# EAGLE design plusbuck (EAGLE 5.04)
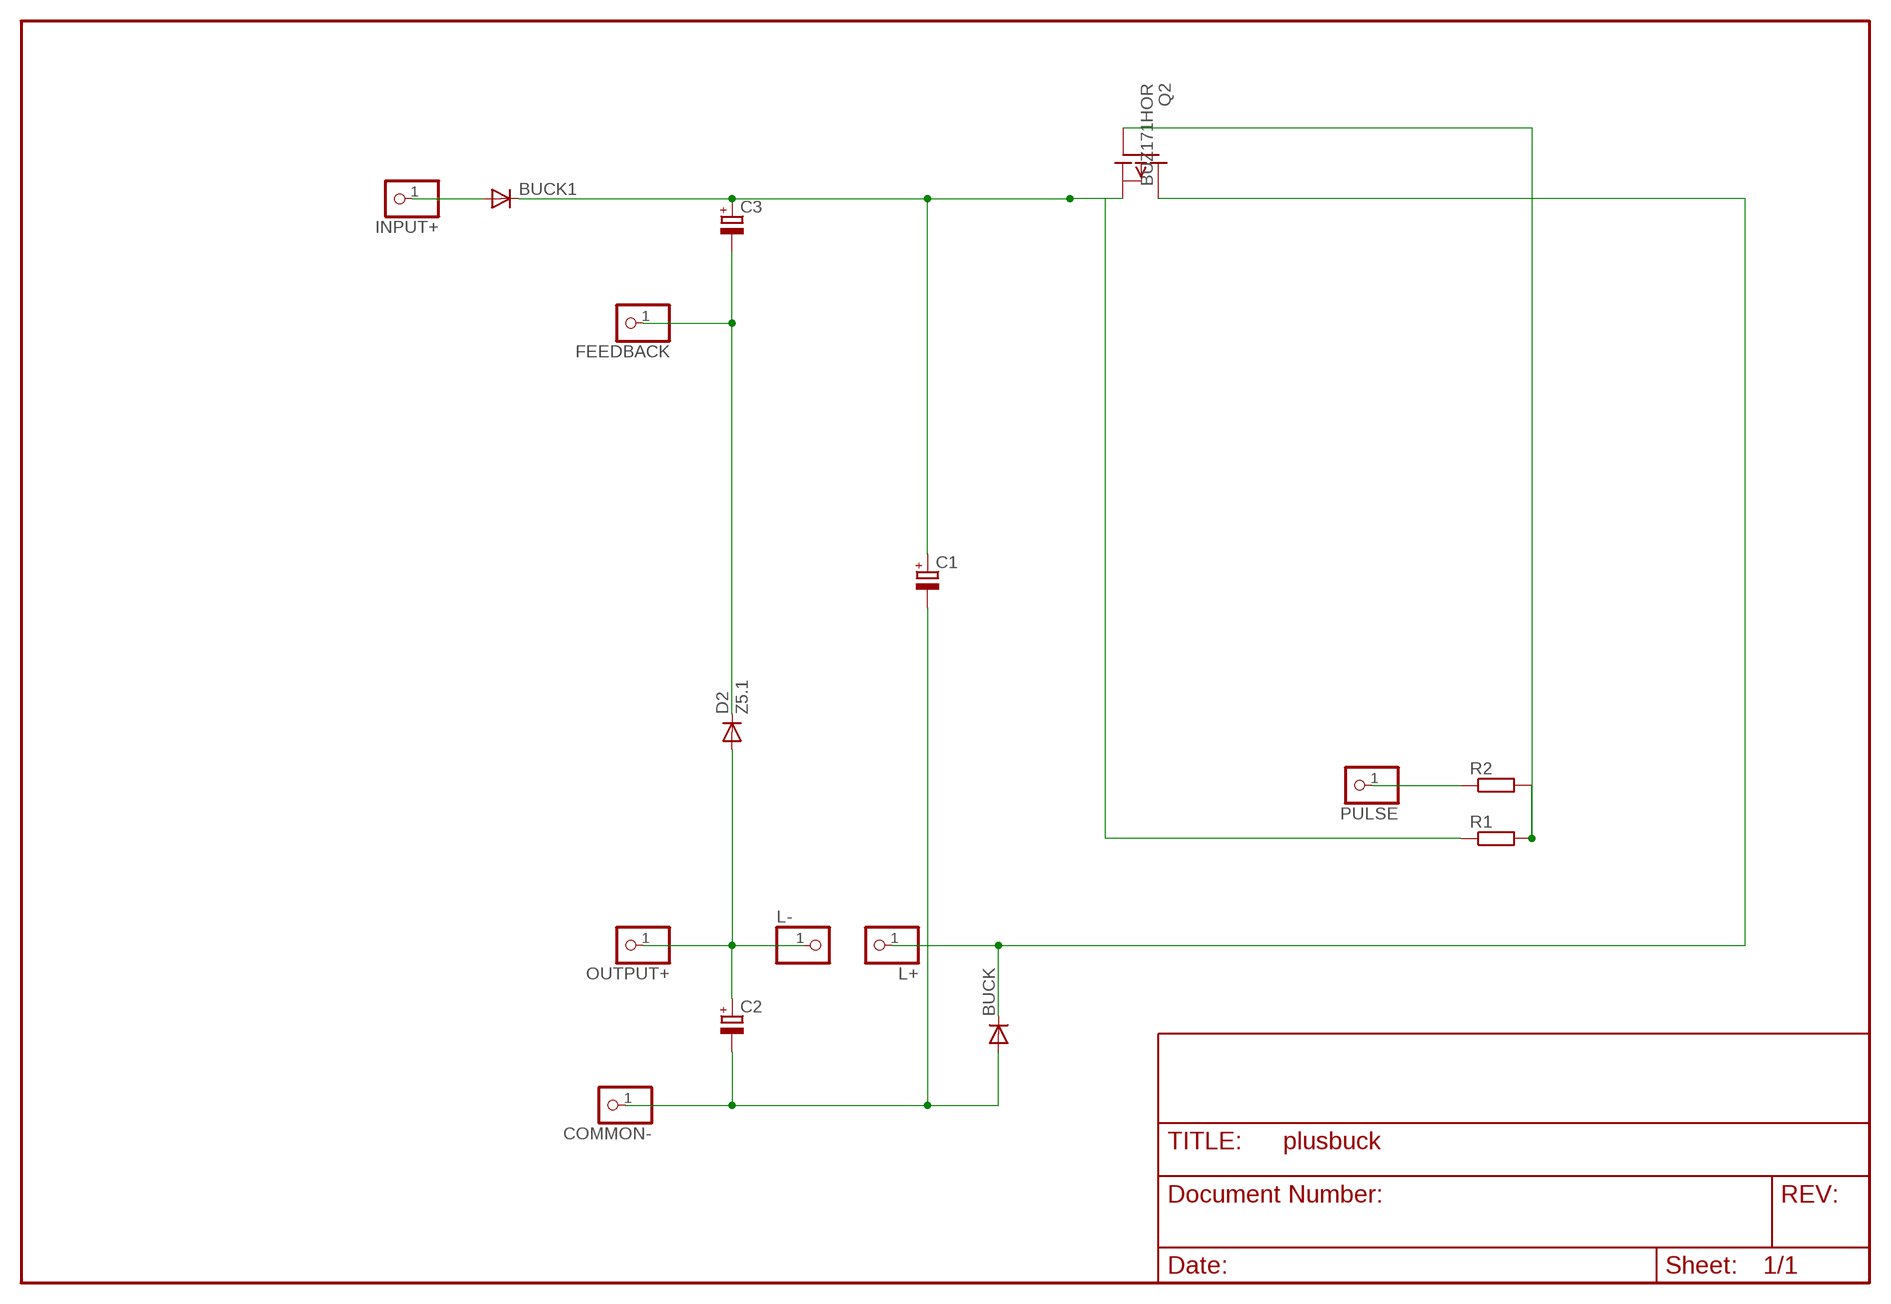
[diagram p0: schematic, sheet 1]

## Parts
BUCK  DIODE-D-10  [D-10]
BUCK1  DIODE-D-10  [D-10]
C1  CPOL-EUE5-13  [E5-13]
C2  CPOL-EUE5-10.5  [E5-10,5]
C3  CPOL-EUE2.5-5  [E2,5-5]
COMMON-  PINHD-1X1  [1X01]
D2  Z5.1  DIODE-D-2.5  [D-2.5]
FEEDBACK  PINHD-1X1  [1X01]
INPUT+  PINHD-1X1  [1X01]
L+  PINHD-1X1  [1X01]
L-  PINHD-1X1  [1X01]
OUTPUT+  PINHD-1X1  [1X01]
PULSE  PINHD-1X1  [1X01]
Q2  BUZ171HOR  [TO220]
R1  R-EU_0204/7  [0204/7]
R2  R-EU_0204/2V  [0204V]

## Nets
GATE: Q2.1(G) R1.2 R2.2
L+: BUCK.C L+.1 Q2.2(D)
L-: C2.+ D2.A L-.1 OUTPUT+.1
N$1: BUCK1.A INPUT+.1
N$2: BUCK.A C1.- C2.- COMMON-.1
N$3: PULSE.1 R2.1
N$9: C3.- D2.C FEEDBACK.1
V+: BUCK1.C C1.+ C3.+ Q2.3(S) R1.1

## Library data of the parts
BUCK BUCK1 D2 = diode:DIODE-: DIODE
C1-C3 = rcl(2):CPOL-EU: POLARIZED CAPACITOR, European symbol
COMMON- FEEDBACK INPUT+ L+ L- OUTPUT+ PULSE = pinhead:PINHD-1X1: PIN HEADER
Q2 = transistor-fet:BUZ171: P-Channel Enhancement MOSFET -50V; 7A; 0,4Ohm
R1 R2 = rcl-2:R-EU_: RESISTOR, European symbol

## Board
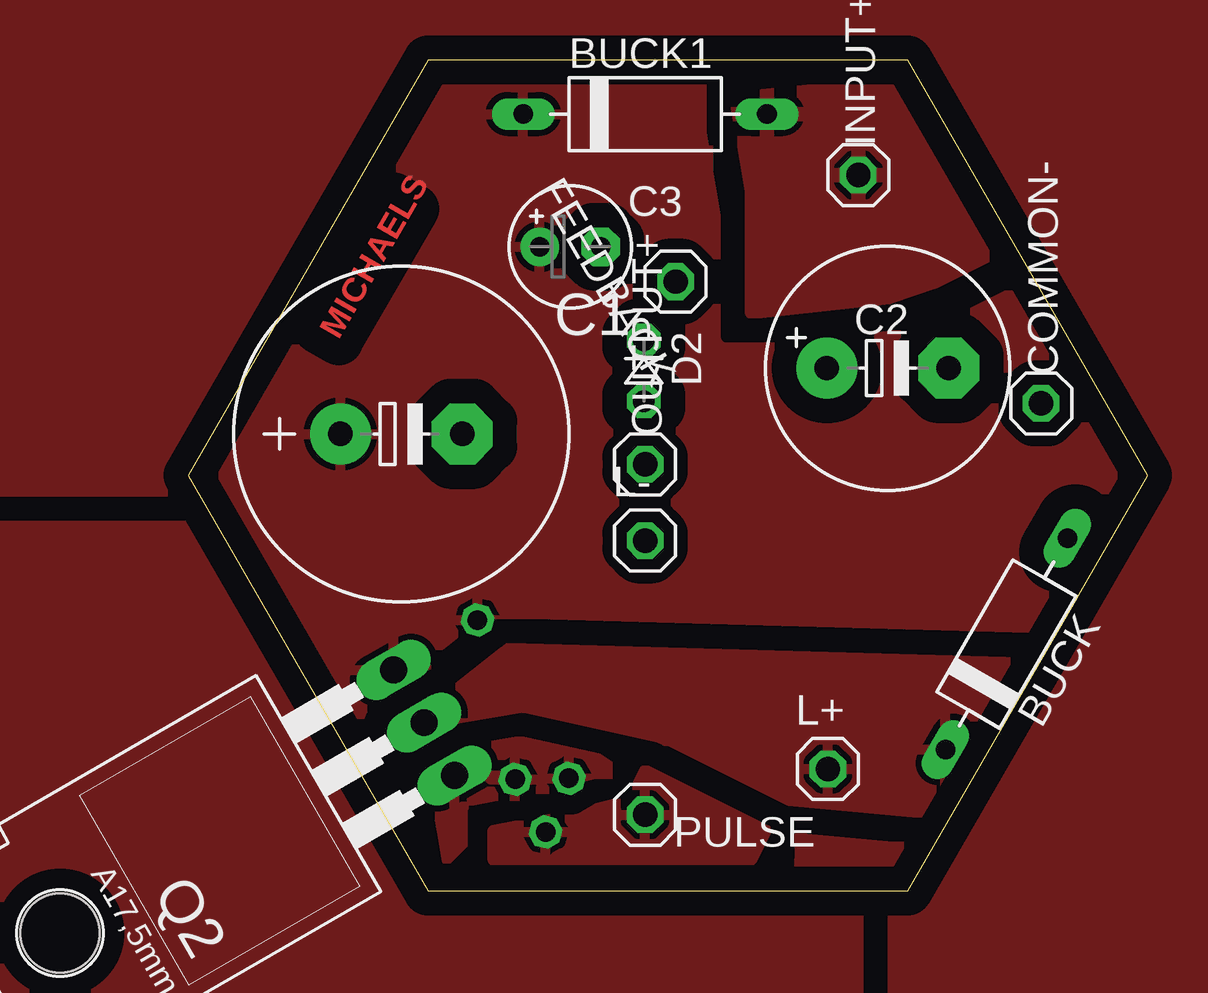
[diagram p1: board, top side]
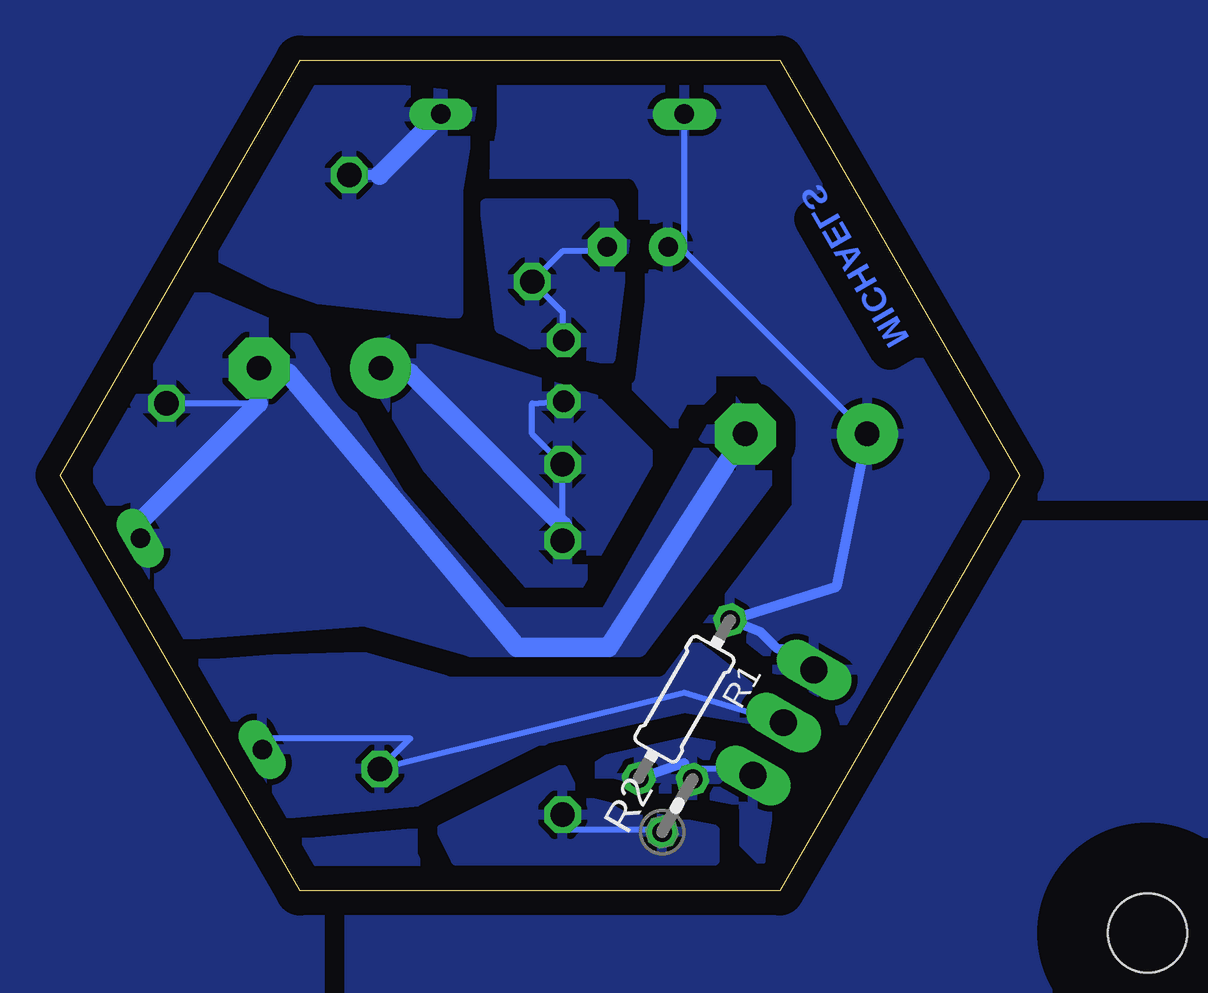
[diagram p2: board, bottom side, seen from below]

Size 40 x 34.64 mm. Coordinates in mm from the lower left corner, seen from the top.
Outline: 10,0 30,0 40,17.32 30,34.64 10,34.64 0,17.32 10,0
Copper layers (1*16): Top 0.035mm / dielectric 1.5mm / Bottom 0.035mm
Design rules "default": minimum track width 10mil, minimum drill 24mil, track to track 8mil, track to pad 8mil, pad to pad 8mil, via to via 8mil, smd to smd 8mil, copper to edge 40mil, drill to drill 8mil, minimum pad ring 10mil, minimum via ring 8mil, stop-mask expansion 4mil, vias tented up to drill 0mil, thermal gap 10mil

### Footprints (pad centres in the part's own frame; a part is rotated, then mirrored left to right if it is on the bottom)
D-10 = drill 0.813 long: A 5.08,0; C -5.08,0
E5-13 = drill 1.016 pad 2.54 round: + -2.54,0 | drill 1.016 pad 2.54 octagon: - 2.54,0
E5-10,5 = drill 1.016 pad 2.54 round: + -2.54,0 | drill 1.016 pad 2.54 octagon: - 2.54,0
E2,5-5 = drill 0.813 pad 1.6 round: + -1.27,0 | drill 0.813 pad 1.6 octagon: - 1.27,0
1X01 = drill 1.016 octagon: 1 0,0
D-2.5 = drill 0.9 octagon: A 1.27,0; C -1.27,0
TO220 = drill 1.118 long: 1 -2.54,-6.35; 2 0,-6.35; 3 2.54,-6.35 | hole 3.302: 0,11.176
0204/7 = drill 0.813 octagon: 1 -3.81,0; 2 3.81,0
0204V = drill 0.813 octagon: 1 -1.27,0; 2 1.27,0

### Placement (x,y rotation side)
BUCK  34.11,10.29 60 top
BUCK1  19.05,32.39 0 top
C1  8.89,19.05 0 top
C2  29.17,21.8 0 top
C3  15.93,26.85 0 top
COMMON-  35.56,20.32 0 top
D2  19,21.68 270 top
FEEDBACK  20.32,25.4 0 top
INPUT+  27.94,29.85 0 top
L+  26.67,5.08 0 top
L-  19.05,14.61 0 top
OUTPUT+  19.05,17.78 0 top
PULSE  19.05,3.17 0 top
Q2  4.34,3.84 120 top
R1  13.97,8 240 bottom
R2  14.27,3.56 60 bottom

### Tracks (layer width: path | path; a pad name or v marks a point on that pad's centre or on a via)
GATE
  Bottom 0.254: R2.2 13.97,5.08 11.43,5.08 Q2.1
  Bottom 0.406: 13.97,5.08 13.97,5.33 R1.2
  pour Bottom (isolate 0.813, rank 3): 10.16,5.08 13.34,6.35 15.88,6.35 17.78,5.08 17.14,3.81 13.34,3.81 11.43,1.91 10.79,1.27
  pour Top (isolate 0.813, rank 3): 10.16,5.08 13.34,6.35 15.88,6.35 17.78,5.08 17.14,3.81 13.34,3.81 11.43,1.91 10.79,1.27
L+
  Bottom 0.254: BUCK.C 31.75,6.35 25.4,6.35 L+.1 13.97,8.25 Q2.2
  pour Bottom (isolate 0.813, rank 2): 10.16,7.62 13.34,10.16 35.56,9.52 31.11,3.17 24.13,3.81 19.68,6.35 13.97,7.62 10.16,6.99
  pour Bottom (isolate 0.406): -10.16,15.24 0,15.24 10.16,0 27.94,0 27.94,-7.62 -10.16,-7.62
  pour Top (isolate 0.406): -10.16,15.24 0,15.24 10.16,0 27.94,0 27.94,-7.62 -10.16,-7.62
  pour Top (isolate 0.813, rank 2): 10.16,7.62 13.34,10.16 35.56,9.52 31.11,3.17 24.13,3.81 19.68,6.35 13.97,7.62 10.16,6.99
L-
  Bottom 0.254: D2.A 20.32,20.32 20.32,19.05 OUTPUT+.1 19.05,15.24 L-.1 | 25.4,21.59 C2.+
  Bottom 0.813: 19.05,15.24 25.4,21.59
  pour Bottom (isolate 0.813, rank 2): 15.24,15.88 15.24,17.78 17.78,20.32 26.04,22.86 27.31,22.22 26.04,18.41 20.32,12.06 17.78,12.06
N$1
  Bottom 0.406: 26.67,29.85 INPUT+.1
  Bottom 0.813: BUCK1.A 26.67,29.85
  pour Bottom (isolate 0.406, rank 2): 22.86,33.02 29.21,33.66 33.66,26.67 31.11,25.4 29.21,24.76 23.5,24.13 23.5,29.21
  pour Top (isolate 0.406, rank 2): 22.86,33.02 29.21,33.66 33.66,26.67 31.11,25.4 29.21,24.76 23.5,24.13 23.5,29.21
N$2
  Bottom 0.254: 36.83,15.24 BUCK.A | COMMON-.1 31.75,20.32 30.48,21.59 C2.-
  Bottom 0.813: 31.75,20.32 36.83,15.24 | C1.- 17.14,10.16 20.95,10.16 30.48,21.59
  pour Bottom (isolate 0.813): 10.16,17.78 15.88,10.16 22.86,10.16 27.31,11.43 35.56,10.79 39.37,17.78 34.29,24.76 29.85,22.86 26.04,16.51 21.59,11.43 17.14,11.43 12.07,20.32
N$3
  Bottom 0.254: R2.1 15.24,2.54 19.05,2.54 PULSE.1
  pour Bottom (isolate 0.813): 12.7,2.54 15.88,3.17 18.41,3.81 19.05,5.08 24.13,2.54 23.5,1.27 12.7,1.27
  pour Top (isolate 0.813): 12.7,2.54 15.88,3.17 18.41,3.81 19.05,5.08 24.13,2.54 23.5,1.27 12.7,1.27
N$9
  Bottom 0.254: D2.C 19.05,22.86 19.05,24.13 FEEDBACK.1 19.05,26.67 17.78,26.67 C3.-
  pour Bottom (isolate 0.406, rank 2): 20.32,22.86 17.14,22.22 16.51,27.3 17.14,28.57 22.22,28.57 21.59,23.49
V+
  Bottom 0.254: 10.16,10.16 8.89,10.16 Q2.3 | 13.97,26.67 BUCK1.C | C1.+ 13.97,26.67 | 13.97,26.67 C3.+
  Bottom 0.406: 8.89,9.52 10.16,10.16 10.79,10.79 R1.1 7.62,12.7 C1.+
  pour Bottom (isolate 0.813, rank 6): -10.16,-7.62 -10.16,50.8 50.8,50.8 50.8,-7.62
  pour Top (isolate 1.016, rank 6): -10.16,-7.62 -10.16,50.8 50.8,50.8 50.8,-7.62

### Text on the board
Top: MICHAELS
Bottom: MICHAELS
